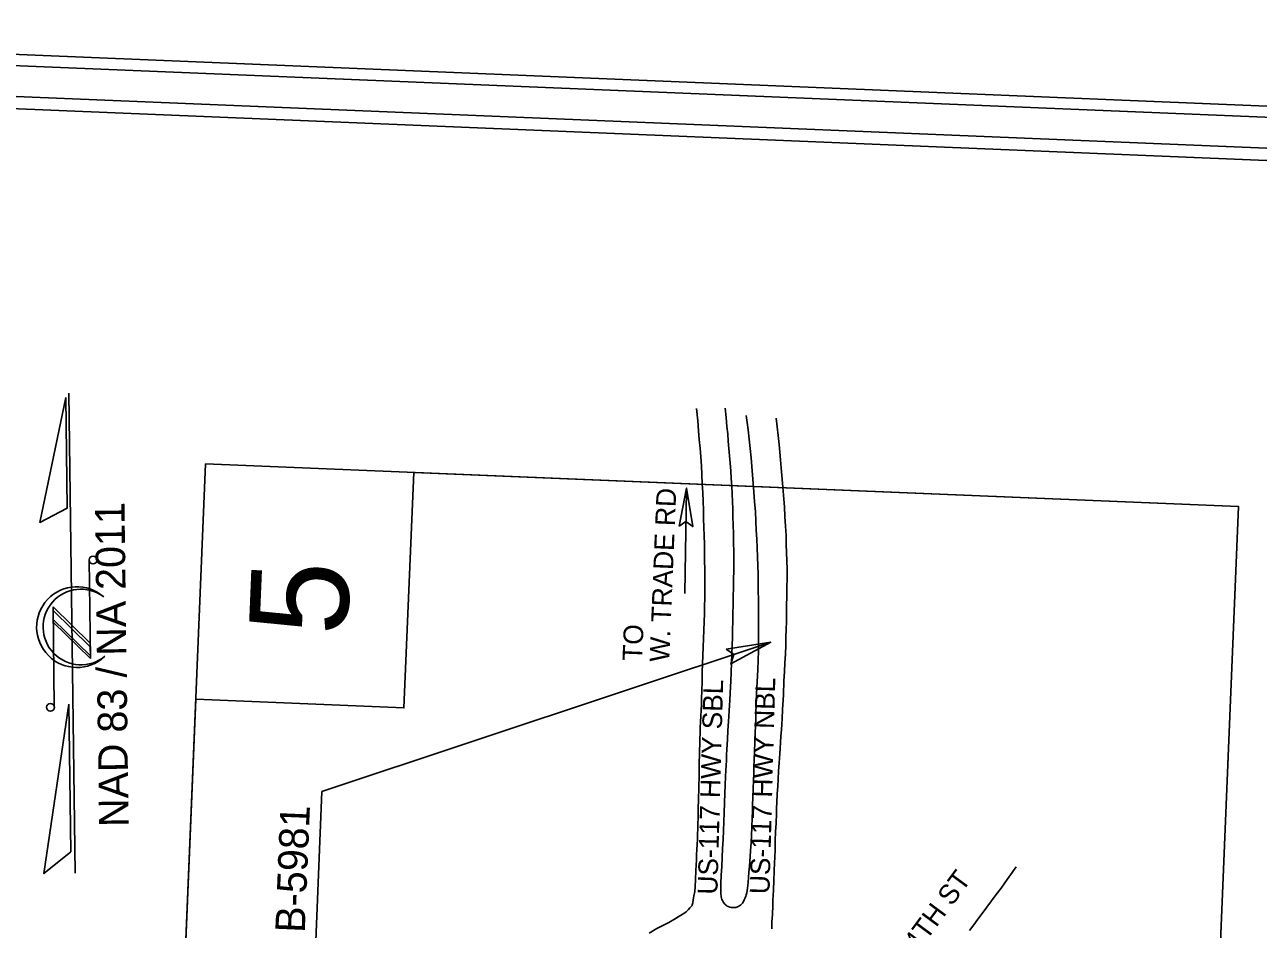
# Model space of a CAD drawing. Extents: x 2264506 to 2267635, y 507918 to 512596.
# Drawn here: x 2265629 to 2266882, y 511677 to 512596 of the extents above; entities that cross this region are included whole.
import ezdxf

# ---------------------------------------------------------------- set-up
doc = ezdxf.new("R2010")
doc.units = 0
for name, color, linetype in [('COGO Default Parcel', 7, 'Continuous'), ('Default', 7, 'Continuous'), ('Exist Structure Minor Drop Inlet Cogo Number', 7, 'Continuous'), ('Prop EOT Dash', 7, 'Continuous'), ('Prop Horizontal Alignment Station Label', 7, 'Continuous'), ('Prop Horizontal Alignment Tick Label', 7, 'Continuous'), ('Prop Horizontal Alignment Tick Large', 7, 'Continuous'), ('Prop Lane Arrow CELL', 7, 'Continuous'), ('Prop Paved Shoulder', 7, 'Continuous'), ('Prop Structure Anchor Unit CELL', 7, 'Continuous'), ('Scratch_Level_1', 7, 'Continuous')]:
    doc.layers.add(name, color=color, linetype=linetype)

msp = doc.modelspace()

# ---------------------------------------------------------------- linework, layer by layer
at = {"layer": 'COGO Default Parcel'}
msp.add_lwpolyline([(2266800.3, 510607.5), (2266862.2, 512106.3), (2266024.4, 512140.9), (2266014.5, 511901.8), (2265803.2, 511910.6), (2265751.2, 510650.9)], close=True, dxfattribs=at)
at = {"layer": 'Exist Structure Minor Drop Inlet Cogo Number'}
for p, q in [((2266299.7, 512018.2), (2266301.5, 512123.4)), ((2266387, 511968.5), (2265931.2, 511816.8)), ((2265931.2, 511816.8), (2265906.8, 511226.8))]:
    msp.add_line(p, q, dxfattribs=at)
at = {"layer": 'Prop EOT Dash'}
msp.add_lwpolyline([(2265695, 509291.6), (2265813.1, 512149.6), (2266862.2, 512106.3), (2266744.1, 509248.2)], close=True, dxfattribs=at)
at = {"layer": 'Prop Horizontal Alignment Station Label'}
for points in [[(2267545.8, 512443.4), (2264973, 512549.7)], [(2267070.7, 512450.5), (2264985, 512536.7)]]:
    msp.add_lwpolyline(points, dxfattribs=at)
at = {"layer": 'Prop Horizontal Alignment Tick Label'}
msp.add_lwpolyline([(2267406.5, 508310.6), (2267578.5, 512473.3), (2264943, 512582.2), (2264771, 508419.5)], close=True, dxfattribs=at)
at = {"layer": 'Prop Horizontal Alignment Tick Large'}
msp.add_lwpolyline([(2264887.3, 512595.8), (2264713.6, 508389.4), (2267461.2, 508275.9), (2267635, 512482.3)], close=True, dxfattribs=at)
at = {"layer": 'Prop Lane Arrow CELL'}
for points in [[(2266340.6, 512206.3), (2266341.6, 512196.9), (2266342.6, 512187.5), (2266343.3, 512180.1), (2266343.9, 512172.8), (2266344.6, 512165.4), (2266345.2, 512157.9), (2266345.9, 512150.3), (2266346.5, 512142.8), (2266347, 512134.9), (2266347.5, 512126.9), (2266347.9, 512119), (2266348.2, 512111.5), (2266348.5, 512103.9), (2266348.7, 512096.4), (2266348.9, 512087.5), (2266349.1, 512078.7), (2266349.3, 512069.8), (2266349.4, 512060.3), (2266349.4, 512050.8), (2266349.5, 512041.2), (2266349.3, 512032.5), (2266349.2, 512023.8), (2266349, 512015.1), (2266348.8, 512006.4), (2266348.6, 511997.7), (2266348.4, 511989.7), (2266348.2, 511981.6), (2266348.1, 511973.5), (2266347.9, 511965.5), (2266347.5, 511956.4), (2266347.2, 511947.2), (2266346.9, 511938.1), (2266346.6, 511929), (2266346, 511917.3)], [(2266317.1, 511918.4), (2266317.1, 511918.4), (2266317.3, 511929.4), (2266317.5, 511938), (2266317.8, 511946.6), (2266318, 511955.2), (2266318.3, 511963.7), (2266318.6, 511972.3), (2266319, 511980.8), (2266319.3, 511989.3), (2266319.7, 511997.9), (2266319.8, 512005.4), (2266320, 512012.9), (2266320.1, 512020.4), (2266320.1, 512028), (2266320, 512035.6), (2266320, 512043.2), (2266319.9, 512050.8), (2266319.8, 512059.5), (2266319.6, 512068.1), (2266319.4, 512076.7), (2266319.2, 512085.3), (2266318.9, 512094), (2266318.7, 512102.7), (2266318.4, 512111.4), (2266318, 512120.5), (2266317.5, 512129.6), (2266317.1, 512138.7), (2266316.6, 512147.8), (2266315.9, 512156.7), (2266315.2, 512165.5), (2266314.5, 512174.3), (2266313.8, 512183.2), (2266313, 512193.3), (2266311.7, 512205.8)], [(2266372.7, 511916.2), (2266373.8, 511940.8), (2266374.2, 511950.3), (2266374.5, 511959.8), (2266374.6, 511968.5), (2266374.6, 511977.3), (2266374.6, 511986.1), (2266374.6, 511994.8), (2266374.7, 512003.6), (2266374.5, 512012.1), (2266374.4, 512020.6), (2266374.3, 512029.2), (2266374.1, 512037.7), (2266374, 512046.2), (2266373.6, 512055.2), (2266373.2, 512064.3), (2266372.8, 512073.3), (2266372.4, 512082.3), (2266372, 512091.4), (2266371.4, 512101.3), (2266370.7, 512111.3), (2266370, 512121.2), (2266369.3, 512129.9), (2266368.6, 512138.5), (2266367.9, 512147.2), (2266367.2, 512155.9), (2266366.2, 512165.3), (2266365.1, 512174.7), (2266364.1, 512184.2), (2266363, 512191.6), (2266362, 512199)], [(2266392.4, 512196.1), (2266393.4, 512187.2), (2266394.5, 512178.4), (2266395.5, 512169.5), (2266396.2, 512161.6), (2266396.9, 512153.7), (2266397.7, 512145.8), (2266398.4, 512137.9), (2266399, 512130), (2266399.6, 512122), (2266400.2, 512114), (2266400.9, 512106), (2266401.4, 512096.3), (2266402, 512086.6), (2266402.6, 512076.8), (2266402.8, 512068.3), (2266403.1, 512059.8), (2266403.4, 512051.3), (2266403.7, 512042.7), (2266403.6, 512033.5), (2266403.5, 512024.3), (2266403.4, 512015), (2266403.2, 512005.8), (2266403.1, 511997.7), (2266402.9, 511989.7), (2266402.7, 511981.6), (2266402.5, 511973.6), (2266402.3, 511965.6), (2266401.9, 511956.5), (2266401.4, 511947.5), (2266401, 511938.5), (2266400.5, 511929.5), (2266400, 511915.1)], [(2266317.1, 511918.4), (2266316.8, 511911.9), (2266316.6, 511905.5), (2266316.3, 511899.4), (2266316, 511893.4), (2266315.8, 511887.6), (2266315.5, 511881.8), (2266315.3, 511876.1), (2266315.1, 511870.4), (2266314.9, 511864.7), (2266314.8, 511859), (2266314.6, 511853.2), (2266314.5, 511847.4), (2266314.4, 511841.6), (2266314.3, 511835.8), (2266314.2, 511830), (2266314.1, 511824.2), (2266313.9, 511817.4), (2266313.8, 511812.7), (2266313.7, 511807), (2266313.5, 511801.3), (2266313.4, 511795.6), (2266313.2, 511790), (2266313.1, 511784.5), (2266312.9, 511779.1), (2266312.7, 511773.7), (2266312.5, 511768.4), (2266312.2, 511763.1), (2266312, 511757.9), (2266311.7, 511752.6), (2266311.5, 511747.4), (2266311.3, 511742.1), (2266311.1, 511736.7), (2266310.7, 511727.3), (2266310.3, 511720.5), (2266309.8, 511715.3), (2266309.1, 511710.7), (2266308.4, 511706.9), (2266307.8, 511703.8), (2266307.3, 511701.8), (2266307.1, 511701.1), (2266306.9, 511700.8), (2266306.3, 511700), (2266305, 511698.7), (2266303.5, 511697.2), (2266302.2, 511695.9), (2266301, 511694.8), (2266299.7, 511693.8), (2266298.1, 511692.7), (2266295.5, 511691), (2266293.1, 511689.5), (2266291.7, 511688.7)], [(2266346, 511917.3), (2266345.6, 511909.4), (2266345.3, 511904.5), (2266344.9, 511899), (2266344.5, 511893.4), (2266344.1, 511888.2), (2266343.6, 511878.9), (2266343.1, 511869.7), (2266342.8, 511864.8), (2266342.5, 511859.6), (2266342.2, 511854.2), (2266342, 511848.8), (2266341.7, 511843.3), (2266341.5, 511837.9), (2266341.2, 511832.6), (2266340.8, 511823.2), (2266340.5, 511815.2), (2266340.1, 511805.5), (2266339.7, 511795.6), (2266339.3, 511786), (2266339, 511777.2), (2266338.6, 511768.2), (2266338.2, 511758.9), (2266337.8, 511749.8), (2266337.3, 511740.9), (2266336.8, 511732.1), (2266336.4, 511723.6), (2266336.2, 511718.4), (2266336.2, 511716.1), (2266336.3, 511713.5), (2266336.7, 511710.1), (2266337, 511708.6), (2266337.4, 511707.3), (2266337.9, 511706.2), (2266339, 511704.3), (2266340.4, 511702.5), (2266341.2, 511701.7), (2266342, 511701.1), (2266342.8, 511700.5), (2266343.7, 511700.1), (2266345.4, 511699.6), (2266346.9, 511699.3), (2266348.4, 511699.1), (2266350, 511699.1), (2266350.8, 511699.1), (2266351.7, 511699.2), (2266352.5, 511699.4), (2266353.3, 511699.7), (2266354.1, 511700.1), (2266354.8, 511700.5), (2266355.6, 511701.1), (2266356.4, 511701.6), (2266357.1, 511702.3), (2266357.7, 511703), (2266358.3, 511703.7), (2266359.3, 511705.3), (2266360.2, 511707), (2266361, 511708.8), (2266361.6, 511710.5), (2266362.2, 511712.1), (2266362.7, 511714.1), (2266363.2, 511716.5), (2266363.5, 511718.9), (2266363.8, 511721.5), (2266364.1, 511725), (2266364.5, 511729.5), (2266364.9, 511734.9), (2266365.3, 511741), (2266365.7, 511746.2), (2266366, 511750.7), (2266366.4, 511756.9), (2266367, 511764.9), (2266367.5, 511772.7), (2266367.9, 511780.5), (2266368.3, 511790.4), (2266368.5, 511796.3), (2266368.6, 511802.2), (2266368.9, 511811.8), (2266369.2, 511819.3), (2266369.5, 511828.9), (2266369.7, 511834.8), (2266369.9, 511841.5), (2266370.2, 511849), (2266370.5, 511857.5), (2266370.9, 511866.9), (2266371.2, 511876.1), (2266371.6, 511884.1), (2266371.8, 511890.8), (2266372, 511896.3), (2266372.4, 511906.1), (2266372.5, 511911.1), (2266372.7, 511916.2)], [(2266388.1, 511677.3), (2266388.1, 511678.4), (2266388.2, 511680.5), (2266388.3, 511684.7), (2266388.7, 511691.9), (2266389, 511701), (2266389.3, 511706.3), (2266389.5, 511711.7), (2266389.7, 511716.9), (2266390.2, 511726.7), (2266390.6, 511736), (2266391, 511745), (2266391.1, 511749.6), (2266391.4, 511758.3), (2266391.7, 511767.1), (2266392, 511776), (2266392.4, 511784.9), (2266392.8, 511794.9), (2266393, 511800.3), (2266393.3, 511805.6), (2266393.7, 511814.6), (2266394.1, 511821.9), (2266394.5, 511829.4), (2266395, 511837.6), (2266395.5, 511846.2), (2266396.2, 511855.4), (2266396.5, 511860.7), (2266396.9, 511866.6), (2266397.4, 511873), (2266397.8, 511879.5), (2266398.2, 511885.4), (2266398.5, 511890.8), (2266399.1, 511900.4), (2266399.7, 511910.1), (2266400, 511915.1)], [(2266589, 511675.8), (2266593.2, 511681.6), (2266597.5, 511687.4), (2266601.7, 511693.2), (2266606.4, 511699.5), (2266611.2, 511705.9), (2266616.1, 511712.3), (2266620.9, 511718.8), (2266624.8, 511724.3), (2266628.7, 511729.8), (2266636.2, 511740.5)], [(2266293.1, 511689.5), (2266289.3, 511687.4), (2266283.5, 511683.8), (2266277.3, 511680.7), (2266271.2, 511677.7), (2266263.5, 511673)]]:
    msp.add_lwpolyline(points, dxfattribs=at)
at = {"layer": 'Prop Paved Shoulder'}
for p, q in [((2265680.5, 511734), (2265674.3, 512221.5)), ((2265694.8, 512052.1), (2265696.1, 511952)), ((2265709.1, 512015), (2265709.6, 512014.6)), ((2265695.9, 511967.6), (2265658.2, 512004.4)), ((2265658.2, 512004.4), (2265659.4, 511902.7)), ((2265695.9, 511964), (2265658.2, 512000.8)), ((2265658.2, 512000.8), (2265658.3, 511991.6)), ((2265696.1, 511954.8), (2265658.3, 511991.6)), ((2265658.3, 511991.6), (2265696.1, 511954.8)), ((2265696.1, 511952), (2265658.4, 511988.8)), ((2265696.1, 511954.8), (2265695.9, 511964))]:
    msp.add_line(p, q, dxfattribs=at)
for points in [[(2265671, 512217.2), (2265644.8, 512090.2), (2265672.4, 512104.7)], [(2265674.3, 511905.7), (2265648.9, 511733.6), (2265676.2, 511755.7)]]:
    msp.add_lwpolyline(points, close=True, dxfattribs=at)
for centre in [(2265698.8, 512052.1), (2265655.5, 511902.5)]:
    msp.add_circle(centre, 3.97, dxfattribs=at)
for centre, radius, start, end in [((2265682.5, 511983.9), 41, 48.5707, 313.1247), ((2265686.5, 511984), 38.4, 53.8257, 309.3594)]:
    msp.add_arc(centre, radius, start, end, dxfattribs=at)
at = {"layer": 'Scratch_Level_1'}
for points in [[(2266294.2, 512086.5), (2266301.5, 512125.1), (2266307.8, 512086), (2266300.9, 512091.1)], [(2266341.8, 511961.6), (2266387, 511968.5), (2266346.5, 511946.6), (2266349.5, 511956)]]:
    msp.add_lwpolyline(points, close=True, dxfattribs=at)

# ---------------------------------------------------------------- texts
at = {"layer": 'Default'}
for s, height, rotation, p in [('5', 100, 87.6342, (2265956.8, 511974.5)), ('US-117 HWY NBL', 20, 88.4291, (2266385.7, 511712.5)), ('US-117 HWY SBL', 20, 88.4291, (2266332.8, 511712)), ('S 4TH ST', 20, 53.5473, (2266521.5, 511632.8))]:
    msp.add_text(s, height=height, rotation=rotation, dxfattribs=at).set_placement(p)
at = {"layer": 'Prop Paved Shoulder'}
msp.add_text('NAD 83 / NA 2011', height=30, rotation=90.7307, dxfattribs=at).set_placement((2265734.9, 511781.1))
at = {"layer": 'Prop Structure Anchor Unit CELL'}
for s, height, p in [('W. TRADE RD', 20, (2266283.9, 511948.2)), ('TO ', 20, (2266256.4, 511949.3)), ('END CONSTRUCTION B-5981', 30, (2265896, 511243.3))]:
    msp.add_text(s, height=height, rotation=87.6342, dxfattribs=at).set_placement(p)

doc.saveas('drawing.dxf')
